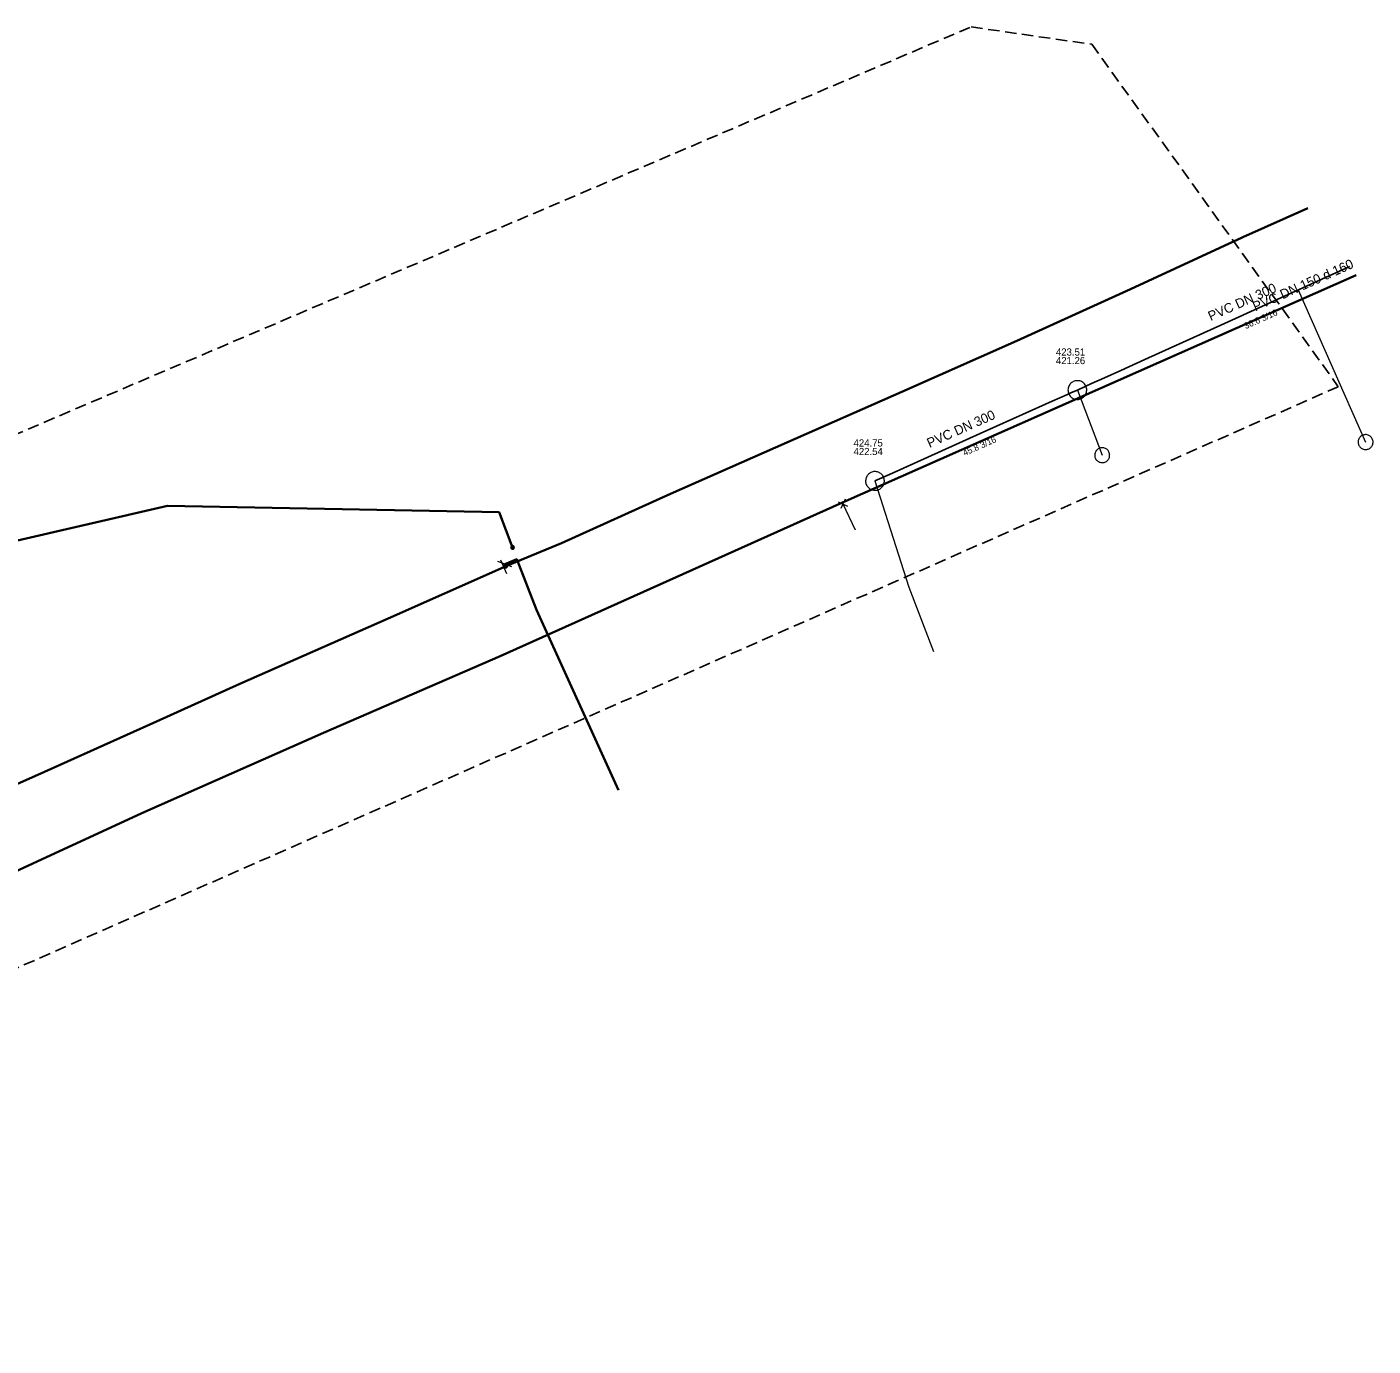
# Model space of a CAD drawing. Extents: x -772868 to -772180, y -1034353 to -1034014.
# Drawn here: x -772349.5 to -772180, y -1034180.3 to -1034014.3 of the extents above; entities that cross this region are included whole.
import ezdxf

# ---------------------------------------------------------------- set-up
doc = ezdxf.new("R2010")
doc.units = 0
doc.header["$LTSCALE"] = 0.48
doc.linetypes.add('MEDIUM_DASHED', pattern=[4.5, 3, -1.5])
for name, color, linetype in [('14', 7, 'Continuous'), ('17', 7, 'Continuous'), ('3', 7, 'Continuous')]:
    doc.layers.add(name, color=color, linetype=linetype)
for name, color, linetype, lineweight in [('15', 7, 'Continuous', 13), ('16', 7, 'Continuous', 35), ('2', 7, 'Continuous', 25), ('4', 7, 'Continuous', 13), ('57', 7, 'Continuous', 13), ('59', 7, 'Continuous', 13), ('62', 7, 'MEDIUM_DASHED', 25)]:
    doc.layers.add(name, color=color, linetype=linetype, lineweight=lineweight)

msp = doc.modelspace()

# ---------------------------------------------------------------- linework, layer by layer
at = {"layer": '15'}
for p, q in [((-772247.357, -1034074.079), (-772246.17, -1034074.613)), ((-772246.5, -1034073.759), (-772247.032, -1034074.934)), ((-772288.452, -1034082.265), (-772290.188, -1034081.593)), ((-772289.066, -1034083.127), (-772289.833, -1034081.431))]:
    msp.add_line(p, q, dxfattribs=at)
for points in [[(-772288.118, -1034079.815), (-772288.124, -1034079.763), (-772288.141, -1034079.713), (-772288.17, -1034079.669), (-772288.207, -1034079.632), (-772288.252, -1034079.605), (-772288.302, -1034079.588), (-772288.355, -1034079.584), (-772288.407, -1034079.591), (-772288.456, -1034079.61), (-772288.499, -1034079.639), (-772288.535, -1034079.678), (-772288.561, -1034079.723), (-772288.577, -1034079.774), (-772288.58, -1034079.826), (-772288.572, -1034079.878), (-772288.552, -1034079.927), (-772288.521, -1034079.97), (-772288.482, -1034080.004), (-772288.436, -1034080.03), (-772288.385, -1034080.044), (-772288.332, -1034080.046), (-772288.281, -1034080.036), (-772288.233, -1034080.015), (-772288.19, -1034079.984), (-772288.156, -1034079.943), (-772288.132, -1034079.897), (-772288.12, -1034079.846)], [(-772288.148, -1034079.815), (-772288.154, -1034079.766), (-772288.171, -1034079.72), (-772288.199, -1034079.68), (-772288.236, -1034079.648), (-772288.28, -1034079.626), (-772288.328, -1034079.615), (-772288.377, -1034079.615), (-772288.424, -1034079.628), (-772288.467, -1034079.652), (-772288.503, -1034079.685), (-772288.53, -1034079.726), (-772288.546, -1034079.773), (-772288.55, -1034079.822), (-772288.543, -1034079.87), (-772288.524, -1034079.915), (-772288.494, -1034079.955), (-772288.456, -1034079.986), (-772288.412, -1034080.006), (-772288.364, -1034080.016), (-772288.315, -1034080.014), (-772288.268, -1034079.999), (-772288.225, -1034079.974), (-772288.191, -1034079.94), (-772288.165, -1034079.898), (-772288.151, -1034079.851)], [(-772288.178, -1034079.815), (-772288.184, -1034079.77), (-772288.201, -1034079.728), (-772288.229, -1034079.693), (-772288.265, -1034079.666), (-772288.307, -1034079.649), (-772288.352, -1034079.644), (-772288.397, -1034079.65), (-772288.438, -1034079.669), (-772288.473, -1034079.697), (-772288.5, -1034079.734), (-772288.516, -1034079.776), (-772288.52, -1034079.821), (-772288.513, -1034079.866), (-772288.494, -1034079.907), (-772288.465, -1034079.941), (-772288.428, -1034079.967), (-772288.385, -1034079.983), (-772288.34, -1034079.986), (-772288.295, -1034079.978), (-772288.255, -1034079.958), (-772288.221, -1034079.929), (-772288.195, -1034079.891), (-772288.181, -1034079.848)], [(-772288.208, -1034079.815), (-772288.213, -1034079.774), (-772288.231, -1034079.737), (-772288.258, -1034079.706), (-772288.293, -1034079.685), (-772288.333, -1034079.674), (-772288.374, -1034079.676), (-772288.413, -1034079.689), (-772288.447, -1034079.713), (-772288.472, -1034079.745), (-772288.487, -1034079.783), (-772288.49, -1034079.824), (-772288.482, -1034079.864), (-772288.462, -1034079.9), (-772288.433, -1034079.929), (-772288.396, -1034079.948), (-772288.356, -1034079.956), (-772288.315, -1034079.952), (-772288.277, -1034079.937), (-772288.245, -1034079.911), (-772288.222, -1034079.877), (-772288.209, -1034079.838)], [(-772288.238, -1034079.815), (-772288.243, -1034079.779), (-772288.261, -1034079.747), (-772288.287, -1034079.722), (-772288.321, -1034079.707), (-772288.357, -1034079.704), (-772288.392, -1034079.712), (-772288.423, -1034079.732), (-772288.446, -1034079.76), (-772288.459, -1034079.794), (-772288.459, -1034079.831), (-772288.448, -1034079.866), (-772288.427, -1034079.895), (-772288.397, -1034079.916), (-772288.362, -1034079.926), (-772288.325, -1034079.924), (-772288.291, -1034079.91), (-772288.264, -1034079.887), (-772288.245, -1034079.855), (-772288.238, -1034079.82)], [(-772288.268, -1034079.815), (-772288.273, -1034079.784), (-772288.29, -1034079.758), (-772288.316, -1034079.741), (-772288.346, -1034079.734), (-772288.377, -1034079.738), (-772288.404, -1034079.755), (-772288.422, -1034079.779), (-772288.43, -1034079.81), (-772288.426, -1034079.84), (-772288.411, -1034079.868), (-772288.387, -1034079.887), (-772288.357, -1034079.896), (-772288.326, -1034079.893), (-772288.298, -1034079.879), (-772288.278, -1034079.855), (-772288.268, -1034079.826)], [(-772288.298, -1034079.815), (-772288.303, -1034079.791), (-772288.32, -1034079.773), (-772288.343, -1034079.764), (-772288.367, -1034079.767), (-772288.388, -1034079.781), (-772288.399, -1034079.803), (-772288.399, -1034079.828), (-772288.387, -1034079.849), (-772288.367, -1034079.863), (-772288.342, -1034079.866), (-772288.319, -1034079.857), (-772288.303, -1034079.839)], [(-772288.328, -1034079.815), (-772288.333, -1034079.8), (-772288.348, -1034079.794), (-772288.363, -1034079.798), (-772288.37, -1034079.812), (-772288.366, -1034079.827), (-772288.353, -1034079.836), (-772288.338, -1034079.833), (-772288.328, -1034079.821)], [(-772288.978, -1034082.17), (-772288.984, -1034082.118), (-772289.001, -1034082.068), (-772289.03, -1034082.024), (-772289.067, -1034081.987), (-772289.112, -1034081.96), (-772289.162, -1034081.943), (-772289.215, -1034081.939), (-772289.267, -1034081.946), (-772289.316, -1034081.965), (-772289.359, -1034081.994), (-772289.395, -1034082.033), (-772289.421, -1034082.078), (-772289.437, -1034082.129), (-772289.44, -1034082.181), (-772289.432, -1034082.233), (-772289.412, -1034082.282), (-772289.381, -1034082.325), (-772289.342, -1034082.359), (-772289.296, -1034082.385), (-772289.245, -1034082.399), (-772289.192, -1034082.401), (-772289.141, -1034082.391), (-772289.093, -1034082.37), (-772289.05, -1034082.339), (-772289.016, -1034082.298), (-772288.992, -1034082.252), (-772288.98, -1034082.201)], [(-772289.008, -1034082.17), (-772289.014, -1034082.121), (-772289.031, -1034082.075), (-772289.059, -1034082.035), (-772289.096, -1034082.003), (-772289.14, -1034081.981), (-772289.188, -1034081.97), (-772289.237, -1034081.97), (-772289.284, -1034081.983), (-772289.327, -1034082.007), (-772289.363, -1034082.04), (-772289.39, -1034082.081), (-772289.406, -1034082.128), (-772289.41, -1034082.177), (-772289.403, -1034082.225), (-772289.384, -1034082.27), (-772289.354, -1034082.31), (-772289.316, -1034082.341), (-772289.272, -1034082.361), (-772289.224, -1034082.371), (-772289.175, -1034082.369), (-772289.128, -1034082.354), (-772289.085, -1034082.329), (-772289.051, -1034082.295), (-772289.025, -1034082.253), (-772289.011, -1034082.206)], [(-772289.038, -1034082.17), (-772289.044, -1034082.125), (-772289.061, -1034082.083), (-772289.089, -1034082.048), (-772289.125, -1034082.021), (-772289.167, -1034082.004), (-772289.212, -1034081.999), (-772289.257, -1034082.005), (-772289.298, -1034082.024), (-772289.333, -1034082.052), (-772289.36, -1034082.089), (-772289.376, -1034082.131), (-772289.38, -1034082.176), (-772289.373, -1034082.221), (-772289.354, -1034082.262), (-772289.325, -1034082.296), (-772289.288, -1034082.322), (-772289.245, -1034082.338), (-772289.2, -1034082.341), (-772289.155, -1034082.333), (-772289.115, -1034082.313), (-772289.081, -1034082.284), (-772289.055, -1034082.246), (-772289.041, -1034082.203)], [(-772289.068, -1034082.17), (-772289.073, -1034082.129), (-772289.091, -1034082.092), (-772289.118, -1034082.061), (-772289.153, -1034082.04), (-772289.193, -1034082.029), (-772289.234, -1034082.031), (-772289.273, -1034082.044), (-772289.307, -1034082.068), (-772289.332, -1034082.1), (-772289.347, -1034082.138), (-772289.35, -1034082.179), (-772289.342, -1034082.219), (-772289.322, -1034082.255), (-772289.293, -1034082.284), (-772289.256, -1034082.303), (-772289.216, -1034082.311), (-772289.175, -1034082.307), (-772289.137, -1034082.292), (-772289.105, -1034082.266), (-772289.082, -1034082.232), (-772289.069, -1034082.193)], [(-772289.098, -1034082.17), (-772289.103, -1034082.134), (-772289.121, -1034082.102), (-772289.147, -1034082.077), (-772289.181, -1034082.062), (-772289.217, -1034082.059), (-772289.252, -1034082.067), (-772289.283, -1034082.087), (-772289.306, -1034082.115), (-772289.319, -1034082.149), (-772289.319, -1034082.186), (-772289.308, -1034082.221), (-772289.287, -1034082.25), (-772289.257, -1034082.271), (-772289.222, -1034082.281), (-772289.185, -1034082.279), (-772289.151, -1034082.265), (-772289.124, -1034082.242), (-772289.105, -1034082.21), (-772289.098, -1034082.175)], [(-772289.128, -1034082.17), (-772289.133, -1034082.139), (-772289.15, -1034082.113), (-772289.176, -1034082.096), (-772289.206, -1034082.089), (-772289.237, -1034082.093), (-772289.264, -1034082.11), (-772289.282, -1034082.134), (-772289.29, -1034082.165), (-772289.286, -1034082.195), (-772289.271, -1034082.223), (-772289.247, -1034082.242), (-772289.217, -1034082.251), (-772289.186, -1034082.248), (-772289.158, -1034082.234), (-772289.138, -1034082.21), (-772289.128, -1034082.181)], [(-772289.158, -1034082.17), (-772289.163, -1034082.146), (-772289.18, -1034082.128), (-772289.203, -1034082.119), (-772289.227, -1034082.122), (-772289.248, -1034082.136), (-772289.259, -1034082.158), (-772289.259, -1034082.183), (-772289.247, -1034082.204), (-772289.227, -1034082.218), (-772289.202, -1034082.221), (-772289.179, -1034082.212), (-772289.163, -1034082.194)], [(-772289.188, -1034082.17), (-772289.193, -1034082.155), (-772289.208, -1034082.149), (-772289.223, -1034082.153), (-772289.23, -1034082.167), (-772289.226, -1034082.182), (-772289.213, -1034082.191), (-772289.198, -1034082.188), (-772289.188, -1034082.176)]]:
    msp.add_lwpolyline(points, close=True, dxfattribs=at)
at = {"layer": '16'}
for points in [[(-772289.209, -1034082.17), (-772289.199, -1034082.165), (-772282.17, -1034079.3), (-772268.48, -1034073.059), (-772253.82, -1034066.62), (-772239.35, -1034060.239), (-772224.899, -1034053.809), (-772210.559, -1034047.3), (-772196.517, -1034040.821), (-772196.449, -1034040.789), (-772188.27, -1034037.121)], [(-772182.189, -1034045.569), (-772246.815, -1034074.175), (-772289.91, -1034093.506), (-772312.151, -1034103.144), (-772325.507, -1034109.06), (-772334.982, -1034113.258), (-772361.953, -1034125.681), (-772401.07, -1034143.8)], [(-772288.349, -1034079.815), (-772290.043, -1034075.397), (-772331.765, -1034074.602), (-772431.111, -1034097.519), (-772432.682, -1034098.491)], [(-772430.254, -1034113.846), (-772424.5, -1034124.91), (-772417.48, -1034138.579), (-772410.32, -1034135.829), (-772393.85, -1034128.53), (-772377.37, -1034121.23), (-772362.42, -1034114.75), (-772348.07, -1034108.44), (-772333.17, -1034101.739), (-772322.649, -1034096.98), (-772303.989, -1034088.78), (-772289.449, -1034082.28)], [(-772289.45, -1034082.28), (-772289.209, -1034082.17), (-772289.32, -1034081.93)], [(-772275.017, -1034110.371), (-772285.333, -1034087.682), (-772287.823, -1034081.296), (-772289.32, -1034081.929)]]:
    msp.add_lwpolyline(points, dxfattribs=at)
at = {"layer": '2'}
for points in [[(-772182.98, -1034044.47), (-772185.571, -1034045.645), (-772198.746, -1034051.617), (-772208.766, -1034056.158), (-772211.794, -1034057.532), (-772213.852, -1034058.465), (-772215.466, -1034059.197), (-772216.194, -1034059.527), (-772217.26, -1034060.01)], [(-772217.26, -1034060.01), (-772217.981, -1034060.334), (-772218.499, -1034060.566), (-772220.415, -1034061.427), (-772221.267, -1034061.809), (-772229.498, -1034065.499), (-772239.127, -1034069.832), (-772240.915, -1034070.634), (-772242.73, -1034071.45)]]:
    msp.add_lwpolyline(points, dxfattribs=at)
at = {"layer": '4'}
for points in [[(-772216.08, -1034060.01), (-772216.086, -1034059.891), (-772216.104, -1034059.774), (-772216.133, -1034059.658), (-772216.174, -1034059.547), (-772216.226, -1034059.44), (-772216.289, -1034059.339), (-772216.362, -1034059.244), (-772216.443, -1034059.158), (-772216.533, -1034059.08), (-772216.631, -1034059.011), (-772216.734, -1034058.953), (-772216.843, -1034058.906), (-772216.957, -1034058.869), (-772217.073, -1034058.844), (-772217.191, -1034058.832), (-772217.31, -1034058.831), (-772217.429, -1034058.842), (-772217.545, -1034058.865), (-772217.659, -1034058.899), (-772217.769, -1034058.945), (-772217.874, -1034059.002), (-772217.972, -1034059.069), (-772218.063, -1034059.145), (-772218.146, -1034059.23), (-772218.22, -1034059.324), (-772218.284, -1034059.424), (-772218.338, -1034059.53), (-772218.381, -1034059.641), (-772218.413, -1034059.755), (-772218.432, -1034059.873), (-772218.44, -1034059.992), (-772218.436, -1034060.11), (-772218.42, -1034060.228), (-772218.392, -1034060.344), (-772218.353, -1034060.456), (-772218.302, -1034060.564), (-772218.241, -1034060.666), (-772218.17, -1034060.762), (-772218.09, -1034060.849), (-772218.001, -1034060.929), (-772217.905, -1034060.999), (-772217.802, -1034061.059), (-772217.694, -1034061.108), (-772217.581, -1034061.146), (-772217.465, -1034061.172), (-772217.347, -1034061.187), (-772217.228, -1034061.19), (-772217.11, -1034061.181), (-772216.992, -1034061.16), (-772216.878, -1034061.127), (-772216.768, -1034061.083), (-772216.662, -1034061.028), (-772216.563, -1034060.962), (-772216.47, -1034060.887), (-772216.386, -1034060.803), (-772216.311, -1034060.711), (-772216.245, -1034060.612), (-772216.189, -1034060.507), (-772216.145, -1034060.397), (-772216.111, -1034060.283), (-772216.09, -1034060.166), (-772216.08, -1034060.047)], [(-772180.044, -1034066.561), (-772180.05, -1034066.455), (-772180.068, -1034066.35), (-772180.097, -1034066.248), (-772180.138, -1034066.15), (-772180.19, -1034066.058), (-772180.252, -1034065.971), (-772180.323, -1034065.893), (-772180.403, -1034065.822), (-772180.49, -1034065.761), (-772180.583, -1034065.711), (-772180.681, -1034065.671), (-772180.784, -1034065.643), (-772180.888, -1034065.626), (-772180.995, -1034065.621), (-772181.1, -1034065.628), (-772181.205, -1034065.647), (-772181.307, -1034065.678), (-772181.404, -1034065.72), (-772181.496, -1034065.773), (-772181.582, -1034065.836), (-772181.66, -1034065.908), (-772181.729, -1034065.988), (-772181.789, -1034066.076), (-772181.839, -1034066.169), (-772181.877, -1034066.268), (-772181.905, -1034066.371), (-772181.92, -1034066.476), (-772181.924, -1034066.582), (-772181.915, -1034066.688), (-772181.895, -1034066.792), (-772181.863, -1034066.893), (-772181.82, -1034066.99), (-772181.766, -1034067.082), (-772181.703, -1034067.167), (-772181.63, -1034067.244), (-772181.549, -1034067.313), (-772181.46, -1034067.371), (-772181.366, -1034067.42), (-772181.267, -1034067.458), (-772181.164, -1034067.484), (-772181.059, -1034067.498), (-772180.952, -1034067.5), (-772180.847, -1034067.491), (-772180.743, -1034067.47), (-772180.642, -1034067.437), (-772180.545, -1034067.392), (-772180.454, -1034067.338), (-772180.37, -1034067.273), (-772180.294, -1034067.199), (-772180.226, -1034067.117), (-772180.168, -1034067.028), (-772180.121, -1034066.933), (-772180.084, -1034066.834), (-772180.059, -1034066.73), (-772180.046, -1034066.625)], [(-772213.197, -1034068.21), (-772213.203, -1034068.104), (-772213.221, -1034067.999), (-772213.25, -1034067.897), (-772213.291, -1034067.799), (-772213.343, -1034067.707), (-772213.405, -1034067.62), (-772213.476, -1034067.542), (-772213.556, -1034067.471), (-772213.643, -1034067.41), (-772213.736, -1034067.36), (-772213.834, -1034067.32), (-772213.937, -1034067.292), (-772214.041, -1034067.275), (-772214.148, -1034067.27), (-772214.253, -1034067.277), (-772214.358, -1034067.296), (-772214.46, -1034067.327), (-772214.557, -1034067.369), (-772214.649, -1034067.422), (-772214.735, -1034067.485), (-772214.813, -1034067.557), (-772214.882, -1034067.637), (-772214.942, -1034067.725), (-772214.992, -1034067.818), (-772215.03, -1034067.917), (-772215.058, -1034068.02), (-772215.073, -1034068.125), (-772215.076, -1034068.231), (-772215.068, -1034068.337), (-772215.048, -1034068.441), (-772215.016, -1034068.542), (-772214.973, -1034068.639), (-772214.919, -1034068.731), (-772214.856, -1034068.816), (-772214.782, -1034068.893), (-772214.701, -1034068.962), (-772214.613, -1034069.02), (-772214.519, -1034069.069), (-772214.42, -1034069.107), (-772214.317, -1034069.133), (-772214.212, -1034069.147), (-772214.105, -1034069.149), (-772214, -1034069.14), (-772213.896, -1034069.119), (-772213.795, -1034069.086), (-772213.698, -1034069.041), (-772213.607, -1034068.987), (-772213.523, -1034068.922), (-772213.447, -1034068.848), (-772213.379, -1034068.766), (-772213.321, -1034068.677), (-772213.274, -1034068.582), (-772213.237, -1034068.483), (-772213.212, -1034068.379), (-772213.199, -1034068.274)], [(-772241.549, -1034071.45), (-772241.556, -1034071.331), (-772241.574, -1034071.214), (-772241.603, -1034071.098), (-772241.644, -1034070.987), (-772241.696, -1034070.88), (-772241.759, -1034070.779), (-772241.831, -1034070.684), (-772241.913, -1034070.598), (-772242.003, -1034070.52), (-772242.101, -1034070.451), (-772242.204, -1034070.393), (-772242.313, -1034070.346), (-772242.427, -1034070.309), (-772242.543, -1034070.284), (-772242.661, -1034070.272), (-772242.78, -1034070.271), (-772242.899, -1034070.282), (-772243.015, -1034070.305), (-772243.129, -1034070.339), (-772243.239, -1034070.385), (-772243.343, -1034070.442), (-772243.442, -1034070.509), (-772243.532, -1034070.585), (-772243.616, -1034070.67), (-772243.69, -1034070.764), (-772243.754, -1034070.864), (-772243.808, -1034070.97), (-772243.851, -1034071.081), (-772243.883, -1034071.195), (-772243.902, -1034071.313), (-772243.91, -1034071.432), (-772243.906, -1034071.55), (-772243.89, -1034071.668), (-772243.862, -1034071.784), (-772243.823, -1034071.896), (-772243.772, -1034072.004), (-772243.711, -1034072.106), (-772243.64, -1034072.202), (-772243.559, -1034072.289), (-772243.471, -1034072.369), (-772243.375, -1034072.439), (-772243.272, -1034072.499), (-772243.164, -1034072.548), (-772243.051, -1034072.586), (-772242.934, -1034072.612), (-772242.817, -1034072.627), (-772242.698, -1034072.63), (-772242.58, -1034072.621), (-772242.462, -1034072.6), (-772242.348, -1034072.567), (-772242.238, -1034072.523), (-772242.132, -1034072.468), (-772242.032, -1034072.402), (-772241.94, -1034072.327), (-772241.856, -1034072.243), (-772241.781, -1034072.151), (-772241.715, -1034072.052), (-772241.659, -1034071.947), (-772241.615, -1034071.837), (-772241.581, -1034071.723), (-772241.559, -1034071.606), (-772241.549, -1034071.487)]]:
    msp.add_lwpolyline(points, close=True, dxfattribs=at)
at = {"layer": '57'}
for p, q in [((-772189.453, -1034047.405), (-772180.984, -1034066.561)), ((-772217.26, -1034060.01), (-772214.137, -1034068.21))]:
    msp.add_line(p, q, dxfattribs=at)
msp.add_lwpolyline([(-772242.73, -1034071.45), (-772238.475, -1034084.815), (-772235.373, -1034092.931)], dxfattribs=at)
at = {"layer": '59'}
for p, q in [((-772246.815, -1034074.175), (-772246.765, -1034074.346)), ((-772246.765, -1034074.346), (-772245.227, -1034077.591))]:
    msp.add_line(p, q, dxfattribs=at)
at = {"layer": '62'}
msp.add_lwpolyline([(-772867.887, -1034286.131), (-772867.882, -1034286.117), (-772230.643, -1034014.315), (-772215.439, -1034016.495), (-772184.418, -1034059.589), (-772836.208, -1034346.326)], close=True, dxfattribs=at)

# ---------------------------------------------------------------- texts
at = {"layer": '14'}
for s, p in [('423.51', (-772219.958, -1034055.677)), ('421.26', (-772219.958, -1034056.754)), ('424.75', (-772245.428, -1034067.117)), ('422.54', (-772245.428, -1034068.194))]:
    msp.add_text(s, height=0.9, dxfattribs=at).set_placement(p)
at = {"layer": '17'}
msp.add_text('PVC DN 150 d 160', height=1.2, rotation=24, dxfattribs=at).set_placement((-772194.851, -1034050.126))
at = {"layer": '3'}
for s, height, p in [('PVC DN 300', 1.2, (-772200.481, -1034051.336)), ('36.6 3/16', 0.8, (-772196.067, -1034052.352)), ('PVC DN 300', 1.2, (-772235.867, -1034067.3)), ('45.8 3/16', 0.8, (-772231.456, -1034068.332))]:
    msp.add_text(s, height=height, rotation=24, dxfattribs=at).set_placement(p)

doc.saveas('drawing.dxf')
